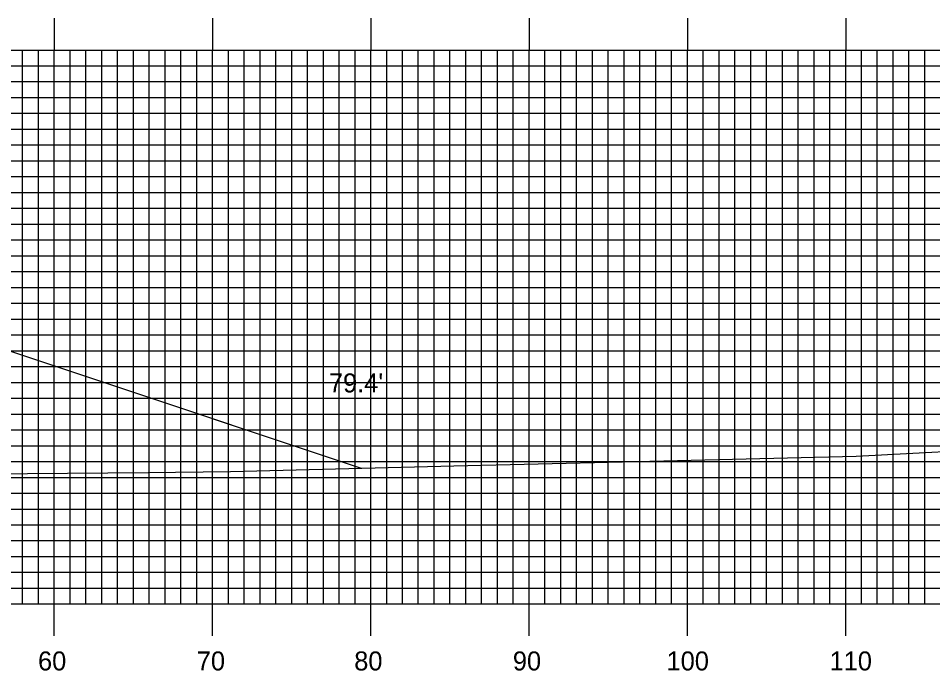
# Model space of a CAD drawing. Extents: x 1789337 to 1789680, y 442591 to 442811.
# Drawn here: x 1789560.4 to 1789618.2, y 442719.4 to 442760.7 of the extents above; entities that cross this region are included whole.
import ezdxf

# ---------------------------------------------------------------- set-up
doc = ezdxf.new("R2010")
doc.units = 0
for name, color, linetype in [('D_Roadway_Centerline', 7, 'Continuous'), ('D_Roadway_SlopeLines', 7, 'Continuous'), ('D_Text_Standard', 7, 'Continuous'), ('H_V ANNOTATION', 7, 'Continuous'), ('MAJOR', 7, 'Continuous'), ('MINOR', 7, 'Continuous'), ('S_Roadway_Centerline', 7, 'Continuous')]:
    doc.layers.add(name, color=color, linetype=linetype)

msp = doc.modelspace()

# ---------------------------------------------------------------- linework, layer by layer
at = {"layer": 'D_Roadway_Centerline'}
msp.add_lwpolyline([(1789437.753, 442729.944), (1789474.92, 442748.527), (1789479.67, 442750.902), (1789482.67, 442751.022), (1789490.67, 442751.342), (1789502.67, 442751.582), (1789514.67, 442751.489), (1789522.67, 442751.169), (1789525.67, 442751.049), (1789532.946, 442748.623), (1789582.06, 442732.252)], dxfattribs=at)
at = {"layer": 'D_Roadway_SlopeLines'}
msp.add_lwpolyline([(1789525.67, 442751.049), (1789582.06, 442732.252)], dxfattribs=at)
at = {"layer": 'MAJOR'}
for p, q in [((1789562.67, 442760.669), (1789562.67, 442758.665)), ((1789572.67, 442760.669), (1789572.67, 442758.665)), ((1789582.67, 442760.669), (1789582.67, 442758.665)), ((1789592.67, 442760.669), (1789592.67, 442758.665)), ((1789602.67, 442760.669), (1789602.67, 442758.665)), ((1789612.67, 442760.669), (1789612.67, 442758.665)), ((1789362.67, 442758.665), (1789642.67, 442758.665)), ((1789362.67, 442758.665), (1789642.67, 442758.665)), ((1789562.67, 442723.665), (1789562.67, 442758.665)), ((1789572.67, 442723.665), (1789572.67, 442758.665)), ((1789582.67, 442723.665), (1789582.67, 442758.665)), ((1789592.67, 442723.665), (1789592.67, 442758.665)), ((1789602.67, 442723.665), (1789602.67, 442758.665)), ((1789612.67, 442723.665), (1789612.67, 442758.665)), ((1789362.67, 442753.665), (1789642.67, 442753.665)), ((1789362.67, 442748.665), (1789642.67, 442748.665)), ((1789362.67, 442743.665), (1789642.67, 442743.665)), ((1789362.67, 442738.665), (1789642.67, 442738.665)), ((1789362.67, 442733.665), (1789642.67, 442733.665)), ((1789362.67, 442728.665), (1789642.67, 442728.665)), ((1789362.67, 442723.665), (1789642.67, 442723.665)), ((1789362.67, 442723.665), (1789642.67, 442723.665)), ((1789562.67, 442721.661), (1789562.67, 442723.665)), ((1789572.67, 442721.661), (1789572.67, 442723.665)), ((1789582.67, 442721.661), (1789582.67, 442723.665)), ((1789592.67, 442721.661), (1789592.67, 442723.665)), ((1789602.67, 442721.661), (1789602.67, 442723.665)), ((1789612.67, 442721.661), (1789612.67, 442723.665))]:
    msp.add_line(p, q, dxfattribs=at)
at = {"layer": 'MINOR'}
for p, q in [((1789560.67, 442723.665), (1789560.67, 442758.665)), ((1789561.67, 442723.665), (1789561.67, 442758.665)), ((1789563.67, 442723.665), (1789563.67, 442758.665)), ((1789564.67, 442723.665), (1789564.67, 442758.665)), ((1789565.67, 442723.665), (1789565.67, 442758.665)), ((1789566.67, 442723.665), (1789566.67, 442758.665)), ((1789567.67, 442723.665), (1789567.67, 442758.665)), ((1789568.67, 442723.665), (1789568.67, 442758.665)), ((1789569.67, 442723.665), (1789569.67, 442758.665)), ((1789570.67, 442723.665), (1789570.67, 442758.665)), ((1789571.67, 442723.665), (1789571.67, 442758.665)), ((1789573.67, 442723.665), (1789573.67, 442758.665)), ((1789574.67, 442723.665), (1789574.67, 442758.665)), ((1789575.67, 442723.665), (1789575.67, 442758.665)), ((1789576.67, 442723.665), (1789576.67, 442758.665)), ((1789577.67, 442723.665), (1789577.67, 442758.665)), ((1789578.67, 442723.665), (1789578.67, 442758.665)), ((1789579.67, 442723.665), (1789579.67, 442758.665)), ((1789580.67, 442723.665), (1789580.67, 442758.665)), ((1789581.67, 442723.665), (1789581.67, 442758.665)), ((1789583.67, 442723.665), (1789583.67, 442758.665)), ((1789584.67, 442723.665), (1789584.67, 442758.665)), ((1789585.67, 442723.665), (1789585.67, 442758.665)), ((1789586.67, 442723.665), (1789586.67, 442758.665)), ((1789587.67, 442723.665), (1789587.67, 442758.665)), ((1789588.67, 442723.665), (1789588.67, 442758.665)), ((1789589.67, 442723.665), (1789589.67, 442758.665)), ((1789590.67, 442723.665), (1789590.67, 442758.665)), ((1789591.67, 442723.665), (1789591.67, 442758.665)), ((1789593.67, 442723.665), (1789593.67, 442758.665)), ((1789594.67, 442723.665), (1789594.67, 442758.665)), ((1789595.67, 442723.665), (1789595.67, 442758.665)), ((1789596.67, 442723.665), (1789596.67, 442758.665)), ((1789597.67, 442723.665), (1789597.67, 442758.665)), ((1789598.67, 442723.665), (1789598.67, 442758.665)), ((1789599.67, 442723.665), (1789599.67, 442758.665)), ((1789600.67, 442723.665), (1789600.67, 442758.665)), ((1789601.67, 442723.665), (1789601.67, 442758.665)), ((1789603.67, 442723.665), (1789603.67, 442758.665)), ((1789604.67, 442723.665), (1789604.67, 442758.665)), ((1789605.67, 442723.665), (1789605.67, 442758.665)), ((1789606.67, 442723.665), (1789606.67, 442758.665)), ((1789607.67, 442723.665), (1789607.67, 442758.665)), ((1789608.67, 442723.665), (1789608.67, 442758.665)), ((1789609.67, 442723.665), (1789609.67, 442758.665)), ((1789610.67, 442723.665), (1789610.67, 442758.665)), ((1789611.67, 442723.665), (1789611.67, 442758.665)), ((1789613.67, 442723.665), (1789613.67, 442758.665)), ((1789614.67, 442723.665), (1789614.67, 442758.665)), ((1789615.67, 442723.665), (1789615.67, 442758.665)), ((1789616.67, 442723.665), (1789616.67, 442758.665)), ((1789617.67, 442723.665), (1789617.67, 442758.665)), ((1789362.67, 442757.665), (1789642.67, 442757.665)), ((1789362.67, 442756.665), (1789642.67, 442756.665)), ((1789362.67, 442755.665), (1789642.67, 442755.665)), ((1789362.67, 442754.665), (1789642.67, 442754.665)), ((1789362.67, 442752.665), (1789642.67, 442752.665)), ((1789362.67, 442751.665), (1789642.67, 442751.665)), ((1789362.67, 442750.665), (1789642.67, 442750.665)), ((1789362.67, 442749.665), (1789642.67, 442749.665)), ((1789362.67, 442747.665), (1789642.67, 442747.665)), ((1789362.67, 442746.665), (1789642.67, 442746.665)), ((1789362.67, 442745.665), (1789642.67, 442745.665)), ((1789362.67, 442744.665), (1789642.67, 442744.665)), ((1789362.67, 442742.665), (1789642.67, 442742.665)), ((1789362.67, 442741.665), (1789642.67, 442741.665)), ((1789362.67, 442740.665), (1789642.67, 442740.665)), ((1789362.67, 442739.665), (1789642.67, 442739.665)), ((1789362.67, 442737.665), (1789642.67, 442737.665)), ((1789362.67, 442736.665), (1789642.67, 442736.665)), ((1789362.67, 442735.665), (1789642.67, 442735.665)), ((1789362.67, 442734.665), (1789642.67, 442734.665)), ((1789362.67, 442732.665), (1789642.67, 442732.665)), ((1789362.67, 442731.665), (1789642.67, 442731.665)), ((1789362.67, 442730.665), (1789642.67, 442730.665)), ((1789362.67, 442729.665), (1789642.67, 442729.665)), ((1789362.67, 442727.665), (1789642.67, 442727.665)), ((1789362.67, 442726.665), (1789642.67, 442726.665)), ((1789362.67, 442725.665), (1789642.67, 442725.665)), ((1789362.67, 442724.665), (1789642.67, 442724.665))]:
    msp.add_line(p, q, dxfattribs=at)
at = {"layer": 'S_Roadway_Centerline'}
msp.add_lwpolyline([(1789555.864, 442731.873), (1789568.605, 442731.978), (1789573.806, 442732.043), (1789587.913, 442732.4), (1789598.568, 442732.636), (1789613.336, 442733.012), (1789623.684, 442733.561), (1789635.39, 442733.548), (1789642.237, 442733.756), (1789642.67, 442733.78)], dxfattribs=at)

# ---------------------------------------------------------------- texts
at = {"layer": 'D_Text_Standard'}
msp.add_text("79.4'", height=1.2, dxfattribs=at).set_placement((1789580.021, 442737.031))
at = {"layer": 'H_V ANNOTATION'}
for s, p in [('60', (1789561.642, 442719.465)), ('70', (1789571.674, 442719.465)), ('80', (1789581.62, 442719.465)), ('90', (1789591.642, 442719.465)), ('100', (1789601.353, 442719.465)), ('110', (1789611.653, 442719.465))]:
    msp.add_text(s, height=1.2, dxfattribs=at).set_placement(p)

doc.saveas('drawing.dxf')
